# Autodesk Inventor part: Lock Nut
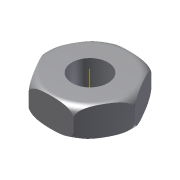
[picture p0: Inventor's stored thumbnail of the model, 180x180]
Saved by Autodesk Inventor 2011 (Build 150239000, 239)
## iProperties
Created: 2009-04
Part Number: Lock Nut
Document SubType Name: Modeling
Designer: Sham
Density: 1 g/cm^3
Author: Sham
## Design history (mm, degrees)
sketch "Sketch1"
  geometry: L1 (7.5, 12.99)-(15, 0); L2 (15, 0)-(7.5, -12.99); L3 (7.5, -12.99)-(-7.5, -12.99); L4 (-7.5, -12.99)-(-15, 0); L5 (-15, 0)-(-7.5, 12.99); L6 (-7.5, 12.99)-(7.5, 12.99); C1 r 6 at (0, 0); 1 further point
  constraints: 12 end point, 1 centre point, 1 coincident, 13 other
  dimensions: "d0" = 30 distance of L1.end L4.end; "d1" = 12 diameter of C1
extrude "Extrusion1" new body sketch "Sketch1" distance "d2" = 10; taper "d3" = 0 deg
sketch "Sketch2"
  geometry: L1 (-12, 0)-(-12, -0.022); L2 (-15, 7)-(-15, 3); L3 (0, -2.87)-(0, 12.87) reference; A1 r 3 centre (-12, 7) between (-12, 10) and (-15, 7); A2 r 3 centre (-12, 3) between (-15, 3) and (-12, 0)
  constraints: 4 end point, 4 point on circle, 2 centre point, 1 tangent
revolve "Revolution1" sketch "Sketch2" stored, may be unused: angle "d7" = 90 deg
body "Solid1"
other parameters: "d6" = 90 deg
